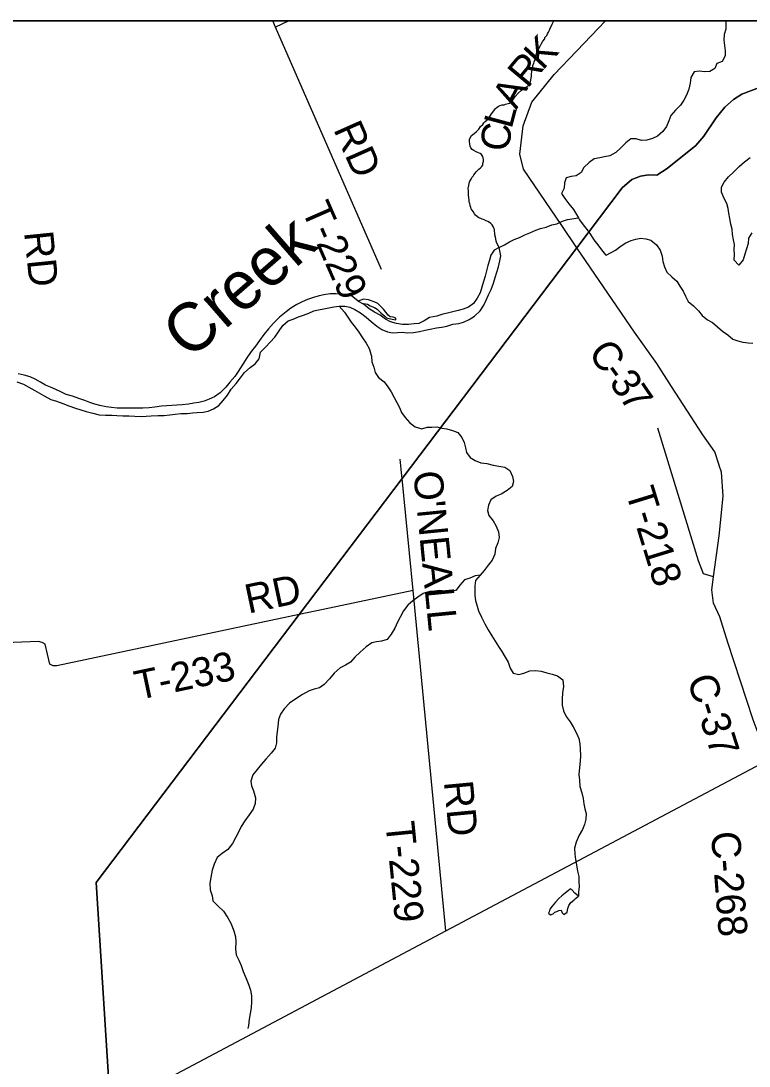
# Model space of a CAD drawing. Extents: x 0.4 to 34.4, y -2.1 to 19.9.
# Drawn here: x 4.924 to 6.349, y 16.79 to 18.836 of the extents above; entities that cross this region are included whole.
import ezdxf

# ---------------------------------------------------------------- set-up
doc = ezdxf.new("R2010")
doc.units = 0
for name, color, linetype in [('GM_X_County', 7, 'Continuous'), ('GM_X_County_Road', 7, 'Continuous'), ('GM_X_County_Road_Text', 7, 'Continuous'), ('GM_X_Major_Lake', 7, 'Continuous'), ('GM_X_Major_River', 7, 'Continuous'), ('GM_X_Major_River_Text', 7, 'Continuous'), ('GM_X_Minor_Lake', 7, 'Continuous'), ('GM_X_Minor_River', 7, 'Continuous'), ('GM_X_Township', 7, 'Continuous'), ('GM_X_Township_Road', 7, 'Continuous'), ('GM_X_Township_Road_Text', 7, 'Continuous'), ('SH_Data', 7, 'Continuous')]:
    doc.layers.add(name, color=color, linetype=linetype)

msp = doc.modelspace()

# ---------------------------------------------------------------- linework, layer by layer
at = {"layer": 'GM_X_County'}
msp.add_lwpolyline([(9.8001, 15.3423), (9.8001, 18.8357), (3.0001, 18.8357), (3.0001, 12.0357), (9.5074, 12.0357)], dxfattribs=at)
at = {"layer": 'GM_X_County_Road'}
for points in [[(6.0116, 18.7768), (6.0681, 18.8357)], [(5.9825, 18.4356), (5.9075, 18.5458), (5.9006, 18.5747), (5.907, 18.6305), (5.9239, 18.6769), (5.9674, 18.7307), (6.0112, 18.7764), (6.0116, 18.7768)], [(6.1972, 18.1203), (6.1972, 18.1203), (6.1683, 18.165), (6.1246, 18.2267), (6.0122, 18.3919), (5.9827, 18.4353), (5.9825, 18.4356)], [(6.2906, 17.9665), (6.2818, 17.9925), (6.2583, 18.0258), (6.1972, 18.1203)], [(5.0993, 16.7069), (5.2822, 16.8039), (5.7558, 17.055), (6.3625, 17.3767), (6.38, 17.386), (6.7247, 17.5708), (6.7542, 17.5855), (6.7786, 17.6112), (6.7991, 17.6537), (6.9135, 17.8219), (6.9221, 17.8335), (6.9343, 17.8393), (6.9503, 17.8402), (7.0217, 17.8445), (7.032, 17.8492), (7.2391, 18.0795)], [(6.38, 17.386), (6.3711, 17.4191), (6.3668, 17.4419), (6.3569, 17.4679), (6.3072, 17.6191), (6.2919, 17.6694), (6.2797, 17.6961), (6.2758, 17.722), (6.2794, 17.7477), (6.2904, 17.8277), (6.2982, 17.9054), (6.2953, 17.9525), (6.2908, 17.9658), (6.2906, 17.9665)]]:
    msp.add_lwpolyline(points, dxfattribs=at)
at = {"layer": 'GM_X_Major_Lake'}
for points in [[(6.3038, 18.8357), (6.3037, 18.8296), (6.3032, 18.8194), (6.3, 18.8088), (6.2994, 18.7978), (6.3008, 18.7876), (6.3025, 18.7769), (6.302, 18.7671), (6.2961, 18.7562), (6.2862, 18.7525), (6.2823, 18.7424), (6.2719, 18.7368), (6.2621, 18.7362), (6.2514, 18.7372), (6.2415, 18.7358), (6.2353, 18.7249), (6.234, 18.7135), (6.2311, 18.7018), (6.2264, 18.6905), (6.221, 18.6808), (6.2151, 18.671), (6.2047, 18.6609), (6.1958, 18.6504), (6.1919, 18.6403), (6.1871, 18.6293), (6.1805, 18.6192), (6.1698, 18.6103), (6.1598, 18.6055), (6.1487, 18.6022), (6.1385, 18.6016), (6.1279, 18.6052), (6.1177, 18.605), (6.1081, 18.5972), (6.0976, 18.5867), (6.088, 18.5782), (6.0762, 18.5715), (6.0662, 18.5694), (6.0567, 18.568), (6.0461, 18.5655), (6.0361, 18.5585), (6.0253, 18.5488), (6.0206, 18.539), (6.0106, 18.5323), (6.0007, 18.531), (5.9908, 18.5285), (5.988, 18.5187), (5.9871, 18.5084), (5.982, 18.4979), (5.9883, 18.488), (5.9965, 18.4776), (6.0051, 18.4668), (6.015, 18.4504)], [(6.3543, 18.4208), (6.3477, 18.4103), (6.3472, 18.4001), (6.344, 18.3899), (6.3408, 18.379), (6.3372, 18.368), (6.329, 18.3579), (6.3201, 18.3675), (6.3202, 18.3785), (6.32, 18.388), (6.3202, 18.3979), (6.3184, 18.4074), (6.3167, 18.4176), (6.3157, 18.4279), (6.3132, 18.4378), (6.3115, 18.4488), (6.3097, 18.4591), (6.308, 18.4686), (6.3055, 18.4785), (6.3003, 18.488), (6.2948, 18.5003), (6.2953, 18.5101), (6.3001, 18.5199), (6.3086, 18.5304), (6.3193, 18.5401), (6.3294, 18.5505), (6.3402, 18.5598), (6.3509, 18.5684)], [(6.015, 18.4504), (6.0173, 18.4465), (6.0243, 18.4366), (6.0321, 18.427), (6.0384, 18.4174), (6.0451, 18.4071), (6.0533, 18.3975), (6.06, 18.3879), (6.0682, 18.3779), (6.0693, 18.3771)], [(6.0693, 18.3771), (6.0877, 18.3867), (6.0985, 18.3952), (6.108, 18.4015), (6.118, 18.4059), (6.1275, 18.4088), (6.137, 18.4106), (6.1469, 18.4093), (6.1567, 18.4068), (6.1679, 18.3972), (6.175, 18.3868), (6.1786, 18.3754), (6.1804, 18.3651), (6.1836, 18.3541), (6.188, 18.3438), (6.1977, 18.3349), (6.2075, 18.3264), (6.2138, 18.3165), (6.2197, 18.3069), (6.2248, 18.297), (6.23, 18.2866), (6.2401, 18.2778), (6.2498, 18.2685), (6.2573, 18.2589), (6.2674, 18.2504), (6.2772, 18.2457), (6.2869, 18.2372), (6.297, 18.2287), (6.3072, 18.2214), (6.3169, 18.2129), (6.3267, 18.2093), (6.3366, 18.2072), (6.3472, 18.2056), (6.3566, 18.2047)]]:
    msp.add_lwpolyline(points, dxfattribs=at)
at = {"layer": 'GM_X_Major_River'}
msp.add_line((5.5837, 18.2875), (5.5938, 18.282), dxfattribs=at)
for points in [[(5.8597, 18.3925), (5.87, 18.3973), (5.8799, 18.4036), (5.8895, 18.408), (5.8994, 18.412), (5.9101, 18.4171), (5.9197, 18.4208), (5.9315, 18.4259), (5.9411, 18.4292), (5.9521, 18.432), (5.9628, 18.4364), (5.9727, 18.4385), (5.9838, 18.4437), (5.9937, 18.4469), (6.015, 18.4504)], [(4.9157, 18.1296), (4.9286, 18.1245), (4.9395, 18.1186), (4.9511, 18.1124), (4.9696, 18.1018), (4.9824, 18.0948), (4.9937, 18.0912), (5.0058, 18.0869), (5.0175, 18.0825), (5.0307, 18.0781), (5.0413, 18.0746), (5.0515, 18.0714), (5.0647, 18.0678), (5.0768, 18.0649), (5.0893, 18.064), (5.1022, 18.0638), (5.1117, 18.0636), (5.1235, 18.0627), (5.1356, 18.0625), (5.1466, 18.0619), (5.1595, 18.0617), (5.169, 18.062), (5.1789, 18.0629), (5.1926, 18.0635), (5.2039, 18.0637), (5.215, 18.0647), (5.226, 18.0664), (5.237, 18.0673), (5.2492, 18.0675), (5.2594, 18.0685), (5.2689, 18.0691), (5.2807, 18.0701), (5.2902, 18.0722), (5.3009, 18.0766), (5.3109, 18.0833), (5.3198, 18.093), (5.3279, 18.1035), (5.3353, 18.1151), (5.345, 18.1263), (5.3535, 18.1372), (5.3616, 18.1473), (5.3724, 18.1574), (5.3824, 18.1644), (5.3901, 18.1746), (5.393, 18.1874), (5.4026, 18.1975), (5.4119, 18.2072), (5.4208, 18.2169), (5.4282, 18.2274), (5.4367, 18.2394), (5.4471, 18.2484), (5.457, 18.252), (5.4673, 18.2564), (5.4769, 18.2597), (5.4876, 18.2637), (5.4971, 18.2681), (5.5066, 18.2702), (5.5165, 18.2723), (5.5264, 18.2744), (5.536, 18.2758), (5.5466, 18.2775), (5.558, 18.2777), (5.5678, 18.2753), (5.5776, 18.271), (5.5885, 18.2644), (5.5994, 18.2559), (5.6095, 18.2474), (5.6204, 18.2381), (5.6302, 18.2319), (5.6411, 18.2275), (5.6509, 18.2255), (5.6608, 18.2257), (5.6703, 18.2263), (5.6802, 18.2254), (5.6919, 18.2256), (5.7038, 18.2281), (5.7152, 18.2302), (5.7247, 18.2323), (5.7373, 18.2351), (5.7475, 18.2365), (5.7574, 18.2386), (5.7693, 18.2422), (5.7807, 18.2436), (5.7902, 18.2464), (5.8013, 18.2512), (5.8116, 18.2579), (5.8228, 18.2683), (5.8298, 18.2792), (5.8345, 18.2894), (5.8392, 18.2999), (5.844, 18.3101), (5.8487, 18.3225), (5.8523, 18.3335), (5.8555, 18.344), (5.8587, 18.3546), (5.8611, 18.3659), (5.8632, 18.3761), (5.8597, 18.3925)], [(5.8597, 18.3925), (5.8501, 18.387), (5.8439, 18.3772), (5.8411, 18.3674), (5.8378, 18.3568), (5.835, 18.3466), (5.8326, 18.336), (5.8294, 18.3258), (5.8262, 18.3149), (5.823, 18.3036), (5.8171, 18.2931), (5.8097, 18.2829), (5.7998, 18.2755), (5.7895, 18.2715), (5.7795, 18.269), (5.7693, 18.2661), (5.759, 18.264), (5.7494, 18.2615), (5.7376, 18.2579), (5.7235, 18.2551), (5.7128, 18.2488), (5.7029, 18.2436), (5.6933, 18.2426), (5.6827, 18.2417), (5.6706, 18.2415), (5.6588, 18.2432), (5.6475, 18.2468), (5.6377, 18.2522), (5.6268, 18.2596), (5.6159, 18.2658), (5.6054, 18.2725), (5.5938, 18.282)], [(5.5837, 18.2875), (5.5705, 18.2984), (5.5595, 18.2997), (5.5496, 18.301), (5.5402, 18.3015), (5.5288, 18.3013), (5.517, 18.2996), (5.5074, 18.2975), (5.4964, 18.2946), (5.4849, 18.2902), (5.4746, 18.2859), (5.4639, 18.2807), (5.4524, 18.2733), (5.4428, 18.2666), (5.4301, 18.2558), (5.4182, 18.2439), (5.4081, 18.233), (5.3992, 18.2218), (5.3911, 18.2102), (5.3829, 18.1993), (5.3744, 18.1884), (5.3663, 18.1761), (5.3585, 18.1637), (5.3491, 18.1498), (5.3425, 18.14), (5.3329, 18.1284), (5.3247, 18.1187), (5.3139, 18.1075), (5.3028, 18.1001), (5.2921, 18.0953), (5.2826, 18.0917), (5.2719, 18.0892), (5.2624, 18.0874), (5.2517, 18.0857), (5.2396, 18.0844), (5.2293, 18.0834), (5.2194, 18.0832), (5.2096, 18.0826), (5.1993, 18.0816), (5.186, 18.0795), (5.1749, 18.0786), (5.1624, 18.0776), (5.1514, 18.0778), (5.1415, 18.0779), (5.132, 18.0777), (5.1218, 18.0779), (5.1119, 18.078), (5.1009, 18.0789), (5.0907, 18.0802), (5.0782, 18.0831), (5.0684, 18.0859), (5.0586, 18.0887), (5.0488, 18.0926), (5.0371, 18.097), (5.0246, 18.101), (5.0121, 18.1046), (5.002, 18.1097), (4.9922, 18.1144), (4.982, 18.1191), (4.9722, 18.1227), (4.962, 18.1285), (4.9515, 18.1344), (4.9417, 18.1391), (4.9304, 18.1423), (4.9186, 18.1447)], [(5.6526, 18.2558), (5.6465, 18.2566), (5.6424, 18.2597), (5.6379, 18.2655), (5.6338, 18.2716), (5.6275, 18.2774), (5.6222, 18.2824), (5.6154, 18.2859), (5.6041, 18.2899), (5.5946, 18.2908), (5.5837, 18.2875)], [(5.5938, 18.282), (5.5953, 18.2825), (5.6021, 18.2812), (5.6077, 18.2781), (5.616, 18.2746), (5.6213, 18.2718), (5.6243, 18.268), (5.6284, 18.2641), (5.6321, 18.261), (5.6363, 18.2579), (5.6396, 18.2549), (5.6442, 18.2536), (5.6472, 18.2528), (5.6506, 18.252), (5.654, 18.2516), (5.6578, 18.2508), (5.6578, 18.2538), (5.6526, 18.2558)]]:
    msp.add_lwpolyline(points, dxfattribs=at)
at = {"layer": 'GM_X_Minor_Lake'}
for points in [[(6.0153, 17.1228), (6.0082, 17.1286), (6.0025, 17.1344), (5.9988, 17.1374), (5.9965, 17.1348), (5.9892, 17.1289), (5.9823, 17.1237), (5.9769, 17.1181), (5.9699, 17.111), (5.9637, 17.1031), (5.9591, 17.0971), (5.9575, 17.0922), (5.9567, 17.0896), (5.9604, 17.0861), (5.9654, 17.0883), (5.9689, 17.0917)], [(5.9689, 17.0917), (5.9727, 17.0931), (5.9769, 17.0949), (5.9811, 17.0953), (5.9829, 17.0903), (5.9866, 17.0872), (5.9928, 17.0913), (5.9944, 17.0985), (5.996, 17.1045), (5.9999, 17.1105), (6.0057, 17.115), (6.0095, 17.1183), (6.0153, 17.1228)]]:
    msp.add_lwpolyline(points, dxfattribs=at)
at = {"layer": 'GM_X_Minor_River'}
for points in [[(5.9221, 18.7198), (5.9225, 18.724), (5.923, 18.7278), (5.9231, 18.7319), (5.9236, 18.7357), (5.9244, 18.741), (5.9257, 18.7448), (5.9261, 18.7482), (5.9278, 18.7528), (5.9282, 18.7558), (5.9294, 18.7588), (5.9307, 18.7638), (5.9315, 18.7664), (5.9331, 18.7721), (5.9348, 18.7762), (5.9371, 18.7796), (5.938, 18.783), (5.9411, 18.7875), (5.9427, 18.7917), (5.9455, 18.7958), (5.949, 18.8003), (5.9495, 18.803), (5.9534, 18.8071), (5.9546, 18.8101), (5.9566, 18.8135), (5.9582, 18.8173), (5.9598, 18.8214), (5.9622, 18.8263), (5.9634, 18.8293), (5.965, 18.832), (5.9662, 18.8346), (5.967, 18.8357)], [(5.8597, 18.3925), (5.8554, 18.4007), (5.8543, 18.4049), (5.8533, 18.4095), (5.8526, 18.4125), (5.8515, 18.4168), (5.8512, 18.4202), (5.8506, 18.424), (5.8506, 18.4274), (5.8496, 18.4301), (5.8481, 18.4336), (5.8463, 18.4366), (5.8437, 18.4393), (5.841, 18.4409), (5.8376, 18.4429), (5.8343, 18.4445), (5.8293, 18.4468), (5.8267, 18.4476), (5.8237, 18.4488), (5.8203, 18.4504), (5.8173, 18.4524), (5.8135, 18.4555), (5.8117, 18.4582), (5.8091, 18.4624), (5.8073, 18.4651), (5.8054, 18.4678), (5.8047, 18.4705), (5.8029, 18.4743), (5.8022, 18.4781), (5.8011, 18.4812), (5.8009, 18.485), (5.8002, 18.49), (5.7999, 18.4945), (5.7997, 18.4995), (5.7997, 18.5037), (5.7995, 18.5079), (5.8003, 18.5135), (5.8012, 18.5181), (5.8025, 18.5223), (5.8052, 18.526), (5.8064, 18.529), (5.8088, 18.532), (5.81, 18.5347), (5.8131, 18.5377), (5.8147, 18.5403), (5.8178, 18.5429), (5.8198, 18.5455), (5.8232, 18.5481), (5.826, 18.5507), (5.8276, 18.5534), (5.828, 18.5568), (5.8289, 18.561), (5.8289, 18.5644), (5.8279, 18.5705), (5.8254, 18.5743), (5.8227, 18.5763), (5.8197, 18.5775), (5.8148, 18.5795), (5.8103, 18.5818), (5.8073, 18.5838), (5.8043, 18.5873), (5.8032, 18.5903), (5.8026, 18.5949), (5.8019, 18.5987), (5.802, 18.6033), (5.8032, 18.6071), (5.806, 18.6112), (5.8107, 18.6153), (5.8157, 18.619), (5.82, 18.6239), (5.8235, 18.6291), (5.8278, 18.6332), (5.8298, 18.6359), (5.8325, 18.6385), (5.8364, 18.6418), (5.8411, 18.6475), (5.8427, 18.6505), (5.8447, 18.6535), (5.8478, 18.6568), (5.8506, 18.6617), (5.8529, 18.6644), (5.8557, 18.667), (5.8584, 18.6688), (5.8618, 18.6703), (5.8657, 18.6714), (5.8695, 18.6717), (5.8722, 18.6724), (5.8776, 18.6738), (5.8806, 18.6749), (5.8834, 18.6779), (5.8861, 18.6801), (5.8877, 18.6827), (5.8912, 18.6876), (5.8971, 18.6944), (5.9033, 18.7003), (5.9076, 18.7033), (5.9118, 18.7063), (5.9165, 18.7089), (5.9185, 18.7122), (5.9208, 18.7149), (5.9221, 18.7198)], [(5.5466, 18.2775), (5.5571, 18.266), (5.5634, 18.256), (5.57, 18.2461), (5.5779, 18.2361), (5.5853, 18.2265), (5.5927, 18.2154), (5.5998, 18.205), (5.6053, 18.1947), (5.61, 18.1795), (5.6106, 18.1685), (5.6146, 18.1578), (5.6175, 18.1479), (5.6238, 18.1379), (5.635, 18.1294), (5.6421, 18.1194), (5.6488, 18.1095), (5.6543, 18.0984), (5.6598, 18.0888), (5.6646, 18.0793), (5.669, 18.0694), (5.6761, 18.0594), (5.685, 18.049), (5.6952, 18.0416), (5.7084, 18.0373), (5.7187, 18.0405), (5.7282, 18.0408), (5.7377, 18.041), (5.7479, 18.0389), (5.7577, 18.0373), (5.7687, 18.0341), (5.7789, 18.0305), (5.7871, 18.0201), (5.7911, 18.0106), (5.794, 18.0003), (5.7961, 17.9908), (5.8028, 17.9812), (5.8126, 17.9757), (5.8242, 17.9706), (5.8356, 17.9697), (5.8481, 17.9661), (5.8594, 17.964), (5.8708, 17.9623), (5.881, 17.9561), (5.8861, 17.9443), (5.8882, 17.9344), (5.8854, 17.9246), (5.8754, 17.9167), (5.8639, 17.9097), (5.854, 17.9053), (5.8436, 17.8987), (5.8389, 17.8877), (5.8368, 17.8775), (5.8394, 17.868), (5.8479, 17.8573), (5.8542, 17.8469), (5.8586, 17.8359), (5.8599, 17.8248), (5.8571, 17.8143), (5.8528, 17.803), (5.8511, 17.7924), (5.846, 17.7803), (5.8386, 17.7706), (5.8308, 17.7604), (5.8227, 17.7507), (5.8138, 17.7406), (5.8125, 17.7304), (5.812, 17.7205), (5.8122, 17.7111), (5.8136, 17.7012), (5.8169, 17.6905), (5.8197, 17.681), (5.8256, 17.6691), (5.8319, 17.6558), (5.8385, 17.6443), (5.8456, 17.6324), (5.8522, 17.6217), (5.8585, 17.6117), (5.8648, 17.6014), (5.8715, 17.5903), (5.8774, 17.5807), (5.8814, 17.5689), (5.8873, 17.5593), (5.8983, 17.5569), (5.9082, 17.559), (5.92, 17.5638), (5.931, 17.5644), (5.9424, 17.5634), (5.953, 17.5602), (5.9639, 17.557), (5.9741, 17.5538), (5.9843, 17.5461), (5.9856, 17.5328), (5.9839, 17.5211), (5.9829, 17.5078), (5.9831, 17.4964), (5.9856, 17.4858), (5.9908, 17.4747), (5.9986, 17.4643), (6.0049, 17.4544), (6.0111, 17.4418)], [(5.8227, 17.7507), (5.8128, 17.7494), (5.8025, 17.7453), (5.7922, 17.7417), (5.7826, 17.7316), (5.776, 17.7215), (5.766, 17.7186), (5.7543, 17.7199), (5.7429, 17.7209), (5.7334, 17.7199), (5.7239, 17.7189), (5.7113, 17.7149), (5.701, 17.7079), (5.6906, 17.7008), (5.681, 17.6926), (5.6725, 17.6814), (5.6658, 17.669), (5.6607, 17.6588), (5.656, 17.6475), (5.6486, 17.6355), (5.6408, 17.625), (5.6298, 17.6221), (5.6199, 17.6208), (5.6104, 17.6183), (5.5993, 17.6108), (5.5877, 17.6), (5.5777, 17.5903), (5.5692, 17.5806), (5.5592, 17.5747), (5.5485, 17.5699), (5.537, 17.5591), (5.5281, 17.5483), (5.5176, 17.537), (5.508, 17.5304), (5.4978, 17.5279), (5.4878, 17.5246), (5.4748, 17.5176), (5.4618, 17.5091), (5.4495, 17.5002), (5.4391, 17.4893), (5.4321, 17.4792), (5.4277, 17.4683), (5.4264, 17.4547), (5.4251, 17.4448), (5.4238, 17.4338), (5.4244, 17.4232), (5.4216, 17.4126), (5.4138, 17.4029), (5.4034, 17.3909), (5.3945, 17.3812), (5.3864, 17.3707), (5.3779, 17.3602), (5.3739, 17.3482), (5.3749, 17.3387), (5.3789, 17.3287), (5.3828, 17.315), (5.3823, 17.304), (5.3787, 17.2931), (5.3709, 17.2818), (5.362, 17.2702), (5.355, 17.2593), (5.3503, 17.2495), (5.3445, 17.2383), (5.3382, 17.2258), (5.3285, 17.2139), (5.3178, 17.2061), (5.3082, 17.1983), (5.3023, 17.1855), (5.2983, 17.1738), (5.2954, 17.1594), (5.2937, 17.1484), (5.2943, 17.1355), (5.2979, 17.1233), (5.2996, 17.1134), (5.309, 17.1038), (5.3202, 17.0934), (5.3291, 17.0807), (5.3346, 17.0697), (5.3405, 17.0548), (5.3437, 17.043), (5.3443, 17.0335), (5.3441, 17.0195), (5.3454, 17.0081), (5.3502, 16.9974), (5.3546, 16.9874), (5.3586, 16.9752), (5.3648, 16.9619), (5.3699, 16.9489), (5.3732, 16.9386), (5.3749, 16.9276), (5.3751, 16.9162), (5.3742, 16.9041), (5.3725, 16.8935), (5.3704, 16.8822), (5.3691, 16.87), (5.3679, 16.864)], [(6.0111, 17.4418), (6.0155, 17.4311), (6.018, 17.4208), (6.0182, 17.4106), (6.0188, 17.398), (6.0186, 17.387), (6.0173, 17.3746), (6.0159, 17.3609), (6.0169, 17.3499), (6.0178, 17.3374), (6.0218, 17.3252), (6.0243, 17.3138), (6.0257, 17.3035), (6.0274, 17.294), (6.0299, 17.2845), (6.0298, 17.2735), (6.0266, 17.2633), (6.023, 17.2535), (6.0164, 17.2422), (6.0105, 17.2287), (6.0076, 17.2169), (6.0082, 17.2048), (6.0092, 17.1949), (6.0113, 17.1839), (6.013, 17.1717), (6.0155, 17.1611), (6.0157, 17.1516), (6.0163, 17.1413), (6.015, 17.1315), (6.0153, 17.1228)]]:
    msp.add_lwpolyline(points, dxfattribs=at)
at = {"layer": 'GM_X_Township'}
for points in [[(6.992, 18.8357), (3.0001, 18.8357), (3.0001, 17.934)], [(6.3726, 18.7066), (6.3351, 18.6926), (6.3186, 18.6819), (6.3016, 18.6667), (6.2844, 18.6458), (6.2602, 18.6098), (6.2451, 18.5916), (6.1884, 18.5471), (6.1688, 18.5339), (6.1521, 18.5342), (6.1365, 18.5318), (6.1196, 18.525), (6.1007, 18.5087), (6.0122, 18.3919), (5.6701, 17.9402), (5.4684, 17.674), (5.0712, 17.1497), (5.0993, 16.7069)], [(5.0993, 16.7069), (5.0712, 17.1497), (5.4684, 17.674), (5.6701, 17.9402), (6.0122, 18.3919), (6.1007, 18.5087), (6.1196, 18.525), (6.1365, 18.5318), (6.1521, 18.5342), (6.1688, 18.5339), (6.1884, 18.5471), (6.2451, 18.5916), (6.2602, 18.6098), (6.2844, 18.6458), (6.3016, 18.6667), (6.3186, 18.6819), (6.3351, 18.6926), (6.3726, 18.7066)]]:
    msp.add_lwpolyline(points, dxfattribs=at)
at = {"layer": 'GM_X_Township_Road'}
for points in [[(5.6299, 18.3489), (5.4222, 18.8235), (5.4169, 18.8357)], [(5.4483, 18.8357), (5.4222, 18.8235)], [(6.2794, 17.7477), (6.2599, 17.7537), (6.25, 17.7792), (6.1705, 18.0386)], [(5.6684, 17.9577), (5.6683, 17.9582), (5.6664, 17.9783)], [(5.7558, 17.055), (5.6914, 17.7211), (5.6701, 17.9402), (5.6684, 17.9577)], [(5.6914, 17.7211), (5.5152, 17.6839)], [(5.5152, 17.6839), (5.5152, 17.6839), (5.4684, 17.674), (4.9943, 17.5739), (4.9867, 17.5733), (4.9803, 17.5768), (4.9713, 17.616), (4.9656, 17.6191), (4.9585, 17.6214), (4.4697, 17.6016)]]:
    msp.add_lwpolyline(points, dxfattribs=at)
at = {"layer": 'SH_Data'}
msp.add_line((3.0001, 18.8357), (9.8001, 18.8357), dxfattribs=at)

# ---------------------------------------------------------------- texts
at = {"layer": 'GM_X_County_Road_Text'}
for s, height, rotation, p in [('K', 0.0568, 47.2183, (5.9448, 18.7375)), ('R', 0.0568, 50.1789, (5.9155, 18.7022)), ('A', 0.0568, 62.0419, (5.8938, 18.6606)), ('L', 0.0568, 75.0366, (5.884, 18.6227)), ('C', 0.0568, 83.0749, (5.8788, 18.5785)), ('C', 0.0568, 304.0289, (6.0327, 18.1873)), ('-', 0.0568, 306.022, (6.06, 18.1469)), ('3', 0.0568, 305.1826, (6.0736, 18.1282)), ('7', 0.0568, 304.1086, (6.0936, 18.0998)), ('C-37', 0.05682, 287.8109, (6.2272, 17.5474)), ('C-268', 0.05682, 274.3994, (6.2743, 17.2479))]:
    msp.add_text(s, height=height, rotation=rotation, dxfattribs=at).set_placement(p)
at = {"layer": 'GM_X_Major_River_Text'}
msp.add_text('Creek', height=0.09469, rotation=41.0566, dxfattribs=at).set_placement((5.2535, 18.1703))
at = {"layer": 'GM_X_Township_Road_Text'}
for s, rotation, p in [('RD', 293.9129, (5.5348, 18.6237)), ('T-229', 293.6768, (5.4724, 18.4667)), ('RD', 275.8105, (4.93, 18.4221)), ("O'NEALL", 275.5818, (5.6917, 17.9527)), ('T-218', 287.1021, (6.1068, 17.914)), ('RD', 11.9919, (5.3689, 17.6756)), ('T-233', 11.9175, (5.1531, 17.5065)), ('RD', 275.4178, (5.7516, 17.3467)), ('T-229', 275.6269, (5.6371, 17.2666))]:
    msp.add_text(s, height=0.05682, rotation=rotation, dxfattribs=at).set_placement(p)

doc.saveas('drawing.dxf')
